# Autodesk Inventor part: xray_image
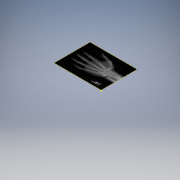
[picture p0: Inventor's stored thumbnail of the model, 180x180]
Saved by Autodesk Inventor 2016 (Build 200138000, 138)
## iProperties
Created: 2015-11
Part Number: xray_image
Material: Generic
Document SubType Name: Modeling
Designer: t_silvdo
Density: 1 g/cm^3
Appearance: Default
Author: t_silvdo
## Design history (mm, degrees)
sketch "Sketch1"
  geometry: L1 (0, 0)-(279.4, 0); L2 (279.4, 0)-(279.4, -215.9); L3 (279.4, -215.9)-(0, -215.9); L4 (0, -215.9)-(0, 0)
  constraints: 8 end point, 2 parallel, 1 horizontal, 1 perpendicular
  dimensions: "d0" = 279.4 distance of L2.end L3.end; "d1" = 215.9 distance of L1.end L2.end
extrude "Extrusion1" new body sketch "Sketch1" distance "d2" = 0.1397; taper "d3" = 0 deg
sketch "Sketch2"
  geometry: L1 (-275.519, 3.627)-(-275.519, 211.933); L2 (-275.519, 211.933)-(-2.737, 211.933); L3 (-2.737, 211.933)-(-2.737, 3.627); L4 (-2.737, 3.627)-(-275.519, 3.627); 1 further point; 1 other entity
  constraints: 2 other
  node "Image2"
sketch "Sketch3"
  geometry: L1 (-279.4, 215.9)-(-279.4, 0) reference; L2 (-279.4, 0)-(0, 0) reference; L3 (0, 215.9)-(-279.4, 215.9) reference; L4 (0, 0)-(0, 215.9) reference; C1 r 3.175 at (-273.05, 6.35); C2 r 3.175 at (-273.05, 209.55); C3 r 3.175 at (-6.35, 6.35); C4 r 3.175 at (-6.35, 209.55)
  constraints: 4 centre point
  dimensions: "d41" = 6.35 diameter of C1; "d42" = 6.35 distance from line of C1.centre L2; "d43" = 6.35 distance from line of C1.centre L1
extrude "Extrusion2" cut sketch "Sketch3" stored distance "d44" = 25.4; taper "d45" = 0 deg
body "Solid1"
